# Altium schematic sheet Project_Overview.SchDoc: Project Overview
size A4; Date: Not used; ApprovedBy: Not used; CheckedBy: Not used; Author: Not used; CompanyName: STMicroelectronics; DrawnBy: Not used; Engineer: Not used; Organization: Not used; Address1: Not used; Address2: Not used; Address3: Not used; Address4: Not used; DocumentNumber: Not used; Revision: Not used; SheetNumber: 1; SheetTotal: 6
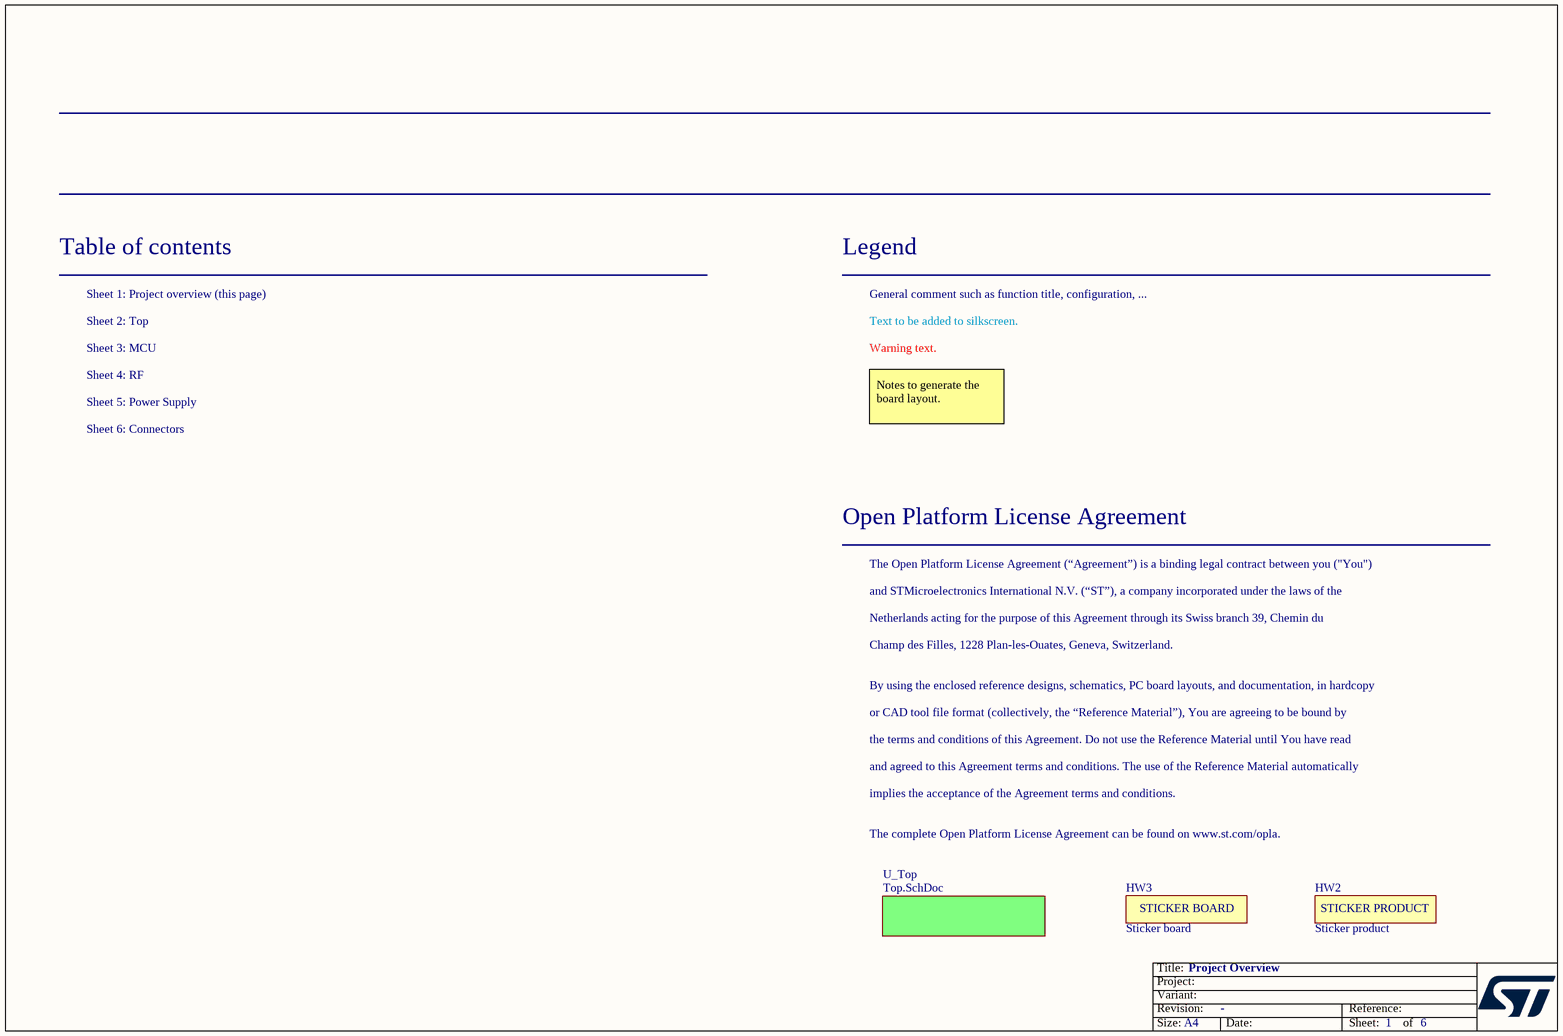
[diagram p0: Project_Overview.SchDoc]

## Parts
HW2  value Sticker product  [STICKER_PRODUCT_25X5]  (hidden comment: STICKER_PRODUCT)  (no BOM)
HW3  value Sticker board  [STICKER_BOARD_25X5]  (hidden comment: STICKER_BOARD)  (no BOM)

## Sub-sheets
U_Top = Top.SchDoc: no entries

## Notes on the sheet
- Table of contents
- Sheet 1: Project overview (this page)
- Legend
- General comment such as function title, configuration, ...
- Sheet 2: Top
- Sheet 3: MCU
- Sheet 4: RF
- Text to be added to silkscreen.
- Warning text.
- Sheet 5: Power Supply
- Sheet 6: Connectors
- Notes to generate the board layout.
- Open Platform License Agreement
- The Open Platform License Agreement (“Agreement”) is a binding legal contract between you ("You")
- and STMicroelectronics International N.V. (“ST”), a company incorporated under the laws of the
- Netherlands acting for the purpose of this Agreement through its Swiss branch 39, Chemin du
- Champ des Filles, 1228 Plan-les-Ouates, Geneva, Switzerland.
- By using the enclosed reference designs, schematics, PC board layouts, and documentation, in hardcopy
- or CAD tool file format (collectively, the “Reference Material”), You are agreeing to be bound by
- the terms and conditions of this Agreement. Do not use the Reference Material until You have read
- and agreed to this Agreement terms and conditions. The use of the Reference Material automatically
- implies the acceptance of the Agreement terms and conditions.
- The complete Open Platform License Agreement can be found on www.st.com/opla.

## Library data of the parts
HW2 = MCD-02189: Sticker product 25x5 mm; Part_Type: Misc; Part_Preference: Recommended; ID: 4289; ShowFields: YES
HW3 = MCD-02190: Sticker board 25x5 mm; Part_Type: Misc; Part_Preference: Recommended; ID: 4290; ShowFields: YES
